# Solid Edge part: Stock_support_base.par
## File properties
Title: Stock Support Base
Author: Abhinav Rai
Template: Normal.par
Last saved by: CADCIM
Revision: 23
Application: Solid Edge
Accuracy: 0.99
Material: aluminum
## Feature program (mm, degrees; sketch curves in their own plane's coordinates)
sketch for "unnamed RevolvedProtrusion 1" plane through (0, 0, 0) normal (0, -1, 0) x-axis (1, 0, 0)
  line (0, 29.2468) -> (71.7103, 29.2468)
  line (71.7103, 29.2468) -> (71.7103, 19.7218)
  line (71.7103, 19.7218) -> (165.1, -256.5032)
  line (165.1, -256.5032) -> (215.9, -256.5032)
  line (215.9, -256.5032) -> (215.9, -281.9032)
  line (215.9, -281.9032) -> (156.9298, -281.9032)
  line (156.9298, -281.9032) -> (85.052, -69.3053)
  arc centre (73.021, -73.3729) radius 12.7 from (60.325, -73.0538) to (85.052, -69.3053) cw
  line (60.325, -73.0538) -> (57.15, -199.3532)
  line (57.15, -199.3532) -> (0, -199.3532)
  line (0, 29.2468) -> (0, -199.3532)
revolve "unnamed RevolvedProtrusion 1" add full turn 360 deg
sketch for "unnamed Hole 1" plane through (0, 0, 29.2468) normal (0, 0, 1) x-axis (1, 0, 0)
  hole centre (0, 0) bore radius 38.1
hole "unnamed Hole 1" through
sketch for "ExtrudedProtrusion_2" plane through (0, 0, -256.5032) normal (0, 0, 1) x-axis (0, 1, 0)
  arc centre (0, -119.2664) radius 41.0756 from (-18.7686, -155.8034) to (18.7686, -155.8034) ccw
  line (-18.7686, -197.1314) -> (-18.7686, -155.8034)
  arc centre (0, -197.1314) radius 18.7686 from (18.7686, -197.1314) to (-18.7686, -197.1314) cw
  line (18.7686, -197.1314) -> (18.7686, -155.8034)
extrude "ExtrudedProtrusion_2" add finite 12.7 along +normal
sketch for "unnamed Hole 2" plane through (187.8036, 0, -243.8032) normal (0, 0, 1) x-axis (1, 0, 0)
hole "unnamed Hole 2" through
fillet "Round_4" radius 3.175
pattern "unnamed Pattern 1" of "ExtrudedProtrusion_2", "unnamed Hole 2", "Round_4"
pattern "unnamed Pattern 2"
sketch for "ExtrudedProtrusion_3" plane through (0, -134.62, 0) normal (0, -1, 0) x-axis (1, 0, 0)
  circle centre (0, -2.5032) radius 19.05
extrude "ExtrudedProtrusion_3" add  Plane_Distance = 134.62 mm
adv blend "unnamed AdvBlend 1"
sketch for "ExtrudedProtrusion_4" plane through (0, -134.62, -2.5032) normal (0, -1, 0) x-axis (1, 0, 0)
  circle centre (0, -3.81) radius 22.225
extrude "ExtrudedProtrusion_4" add finite 9.525 along +normal
mirror "unnamed Mirror 1" of "ExtrudedProtrusion_4", "unnamed AdvBlend 1", "ExtrudedProtrusion_3" about plane through (0, 0, 0) normal (0, -1, 0)
extrude "unnamed Protrusion 1" add
adv blend "unnamed AdvBlend 2"
extrude "unnamed Protrusion 2" add finite 9.525
sketch for "ExtrudedProtrusion_7" plane through (104.775, 0, 0) normal (1, 0, 0) x-axis (0, 1, 0)
  circle centre (0, -167.6032) radius 19.05
extrude "ExtrudedProtrusion_7" add finite 41.275 along +normal  Plane_Distance = 104.775 mm
sketch for "unnamed Hole 3" plane through (146.05, 0, -167.6032) normal (1, 0, 0) x-axis (0, 1, 0)
  hole centre (0, 0) bore radius 7.9375
hole "unnamed Hole 3" through
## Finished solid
Body 1: solid body, 54 faces, 95 edges, 41 vertices.
  Faces by surface: plane 26, cylinder 19, torus 4, cone 3, blend 2
  Edges by curve: circle 57, intersection 20, line 18
Bounding box of the edges (mm; curved faces can reach further): 431.800 x 431.800 x 311.150, from (-215.9, -215.9, -281.9032) to (215.9, 215.9, 29.2468).
Cylindrical faces by radius (mm): R7.9375 x1, R11.1125 x3, R15.875 x3, R18.7686 x3, R19.05 x4, R22.225 x2, R38.1 x1, R71.7103 x1, R215.9 x1
Conical faces (half-angle, radius in mm at the cone's reference point): 1.44 deg R60.325 x1, 18.68 deg R71.7103 x1, 18.68 deg R156.9298 x1
Toroidal faces (ring radius, tube radius in mm): R73.021 r12.7 x1, R163.0843 r3.175 x3
Planar faces by outward normal: +x 1, +y 4, +z 10, -x 1, -y 4, -z 2, oblique 4
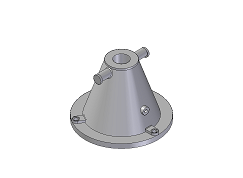
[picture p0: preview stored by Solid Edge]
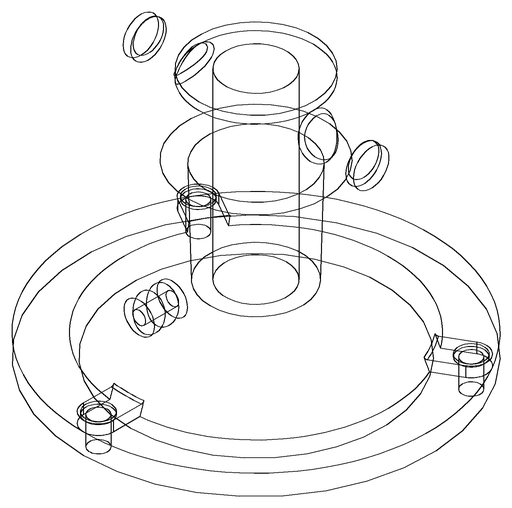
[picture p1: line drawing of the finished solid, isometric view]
